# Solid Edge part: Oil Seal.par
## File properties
Title: OIL SEAL 35,52,7
Author: Dan
Template: Normal.par
Last saved by: Dan
Revision: 2
Application: Solid Edge
Density: 0 kg/mm^3
Accuracy: 0.99
Document Number: P52-022
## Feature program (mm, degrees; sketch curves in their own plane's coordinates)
sketch for "unnamed RevolvedProtrusion 1" plane through (0, 0, 0) normal (0, -1, 0) x-axis (1, 0, 0)
  line (0, 26) -> (7, 26)
  line (7, 26) -> (7, 17.5)
  line (7, 17.5) -> (0, 17.5)
  line (0, 17.5) -> (0, 26)
revolve "unnamed RevolvedProtrusion 1" add finite 360 deg
thinwall "unnamed Thinwall 1"
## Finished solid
Body 1: solid body, 8 faces, 8 edges, 0 vertices.
  Faces by surface: cylinder 4, plane 4
  Edges by curve: circle 8
Bounding box of the edges (mm): 7.000 x 52.000 x 52.000, from (0, -26, -26) to (7, 26, 26).
Cylindrical faces by radius (mm): R17.5 x1, R19 x1, R24.5 x1, R26 x1
Planar faces by outward normal: +x 1, -x 3
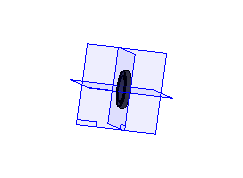
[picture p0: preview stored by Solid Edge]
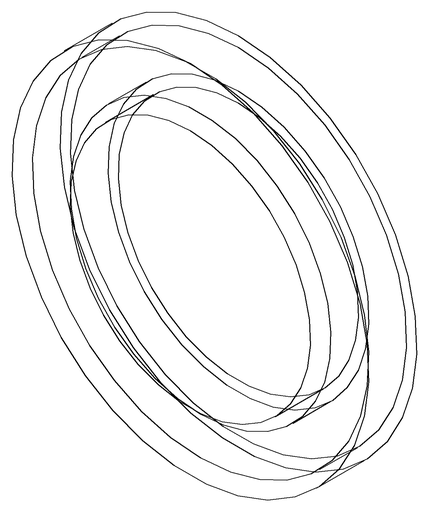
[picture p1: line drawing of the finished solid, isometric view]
